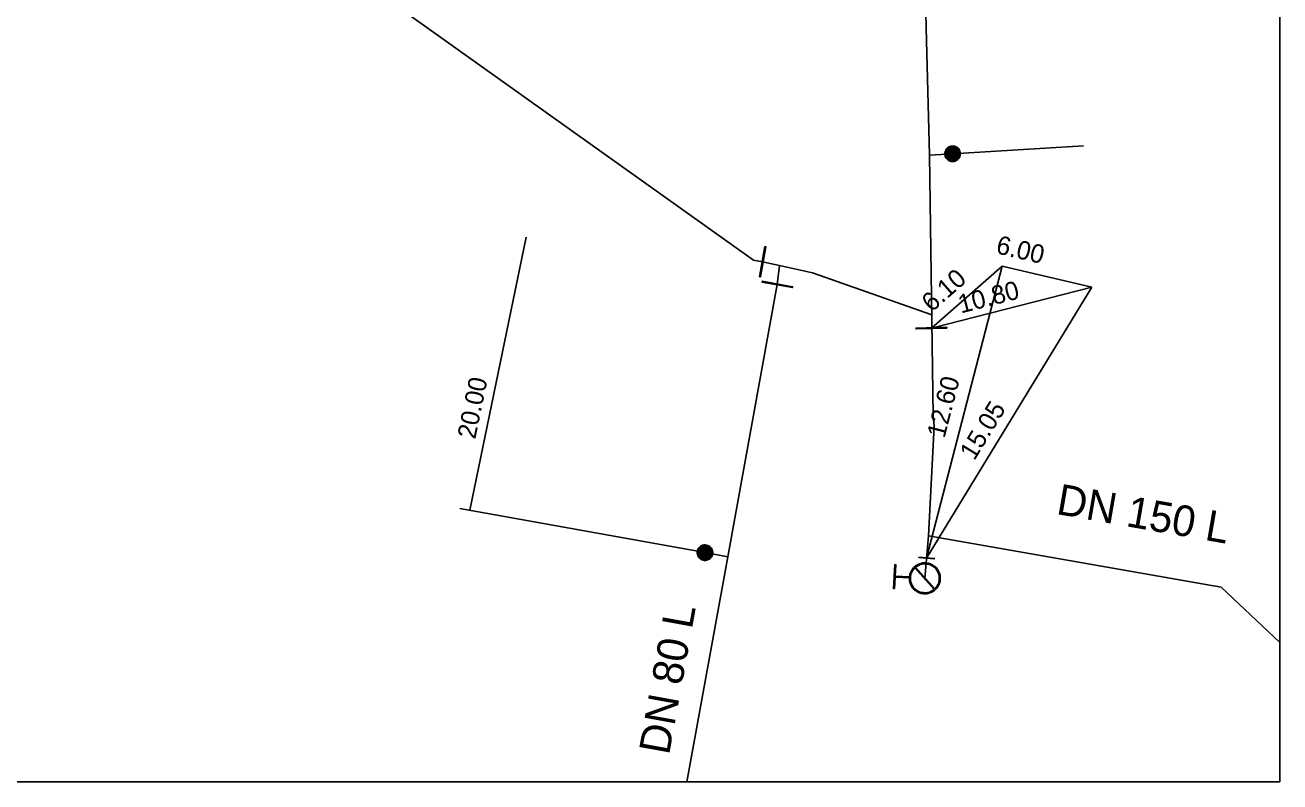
# Model space of a CAD drawing. Extents: x -820257 to -819974, y -1070894 to -1070484.
# Drawn here: x -820057.3 to -819975.6, y -1070893.9 to -1070844.7 of the extents above; entities that cross this region are included whole.
import ezdxf

# ---------------------------------------------------------------- set-up
doc = ezdxf.new("R2010")
doc.units = 0
for name, color, linetype in [('Default', 7, 'Continuous'), ('Hyd-odbočka', 7, 'Continuous'), ('Hyd-šoupě', 7, 'Continuous'), ('Hydrant', 7, 'Continuous'), ('Oměrka vodovodu', 7, 'Continuous'), ('Oměrka-text', 7, 'Continuous'), ('Přípojka vodovodu', 7, 'Continuous'), ('Přípojkový uzávěr', 7, 'Continuous'), ('Roz-řad', 7, 'Continuous'), ('Roz-řad-popis základní', 7, 'Continuous'), ('Řad-šoupě', 7, 'Continuous')]:
    doc.layers.add(name, color=color, linetype=linetype)

msp = doc.modelspace()

# ---------------------------------------------------------------- linework, layer by layer
at = {"layer": 'Default'}
for p, q in [((-819975.603, -1070893.932), (-819975.603, -1070484.403)), ((-820256.81, -1070893.932), (-819975.603, -1070893.932))]:
    msp.add_line(p, q, dxfattribs=at)
at = {"layer": 'Hyd-odbočka'}
msp.add_line((-819998.473, -1070877.929), (-819998.717, -1070880.686), dxfattribs=at)
at = {"layer": 'Hyd-šoupě'}
msp.add_lwpolyline([(-819999.097, -1070879.303), (-819998.101, -1070879.391), (-819998.103, -1070879.422), (-819999.099, -1070879.334), (-819999.097, -1070879.303)], dxfattribs=at)
at = {"layer": 'Hydrant'}
for points in [[(-819999.717, -1070880.661), (-820000.653, -1070880.609), (-820000.695, -1070881.358), (-820000.757, -1070881.354), (-820000.67, -1070879.794), (-820000.607, -1070879.798), (-820000.649, -1070880.546), (-819999.713, -1070880.599)], [(-819998.113, -1070881.407), (-819999.365, -1070880.006)], [(-819999.32, -1070879.966), (-819998.066, -1070881.366)]]:
    msp.add_lwpolyline(points, dxfattribs=at)
for points in [[(-819999.713, -1070880.599), (-819999.692, -1070880.363), (-819999.559, -1070880.146), (-819999.417, -1070879.915), (-819999.169, -1070879.794), (-819998.922, -1070879.673), (-819998.661, -1070879.688), (-819998.401, -1070879.702), (-819998.171, -1070879.847), (-819997.94, -1070879.992), (-819997.822, -1070880.238), (-819997.704, -1070880.483), (-819997.718, -1070880.742), (-819997.733, -1070881.002), (-819997.878, -1070881.232), (-819998.023, -1070881.463), (-819998.268, -1070881.581), (-819998.513, -1070881.699), (-819998.773, -1070881.685), (-819999.034, -1070881.67), (-819999.266, -1070881.522), (-819999.499, -1070881.374), (-819999.614, -1070881.129), (-819999.722, -1070880.9), (-819999.717, -1070880.661)], [(-819999.365, -1070880.006), (-819999.446, -1070880.084), (-819999.506, -1070880.18), (-819999.639, -1070880.398), (-819999.653, -1070880.634), (-819999.666, -1070880.87), (-819999.558, -1070881.101), (-819999.449, -1070881.332), (-819999.232, -1070881.47), (-819999.015, -1070881.608), (-819998.769, -1070881.622), (-819998.525, -1070881.636), (-819998.296, -1070881.524), (-819998.196, -1070881.476), (-819998.113, -1070881.407)], [(-819998.066, -1070881.366), (-819997.99, -1070881.292), (-819997.932, -1070881.198), (-819997.794, -1070880.982), (-819997.781, -1070880.739), (-819997.767, -1070880.495), (-819997.878, -1070880.265), (-819997.99, -1070880.035), (-819998.205, -1070879.899), (-819998.42, -1070879.764), (-819998.664, -1070879.75), (-819998.91, -1070879.736), (-819999.141, -1070879.851), (-819999.24, -1070879.9), (-819999.32, -1070879.966)]]:
    msp.add_open_spline(points, degree=3, dxfattribs=at)
at = {"layer": 'Oměrka vodovodu'}
for p, q in [((-820028.34, -1070876.249), (-820024.68, -1070858.484)), ((-819998.6, -1070879.363), (-819993.684, -1070860.366)), ((-819998.29, -1070864.406), (-819993.684, -1070860.366)), ((-819993.684, -1070860.366), (-819987.841, -1070861.73)), ((-819998.6, -1070879.363), (-819987.841, -1070861.73)), ((-819998.29, -1070864.406), (-819987.841, -1070861.73))]:
    msp.add_line(p, q, dxfattribs=at)
at = {"layer": 'Přípojka vodovodu'}
for points in [[(-819998.405, -1070853.152), (-819996.908, -1070853.059), (-819988.393, -1070852.533)], [(-820011.552, -1070879.28), (-820013.027, -1070879.013), (-820028.996, -1070876.131)]]:
    msp.add_lwpolyline(points, dxfattribs=at)
at = {"layer": 'Přípojkový uzávěr'}
for points in [[(-819996.939, -1070852.56), (-819996.813, -1070852.552), (-819996.69, -1070852.609), (-819996.567, -1070852.666), (-819996.492, -1070852.782), (-819996.417, -1070852.898), (-819996.409, -1070853.029), (-819996.401, -1070853.158), (-819996.459, -1070853.281), (-819996.518, -1070853.404), (-819996.632, -1070853.477), (-819996.747, -1070853.55), (-819996.877, -1070853.558), (-819997.007, -1070853.566), (-819997.13, -1070853.508), (-819997.253, -1070853.449), (-819997.326, -1070853.335), (-819997.399, -1070853.22), (-819997.407, -1070853.09), (-819997.415, -1070852.96), (-819997.355, -1070852.836), (-819997.296, -1070852.711), (-819997.181, -1070852.64), (-819997.065, -1070852.568), (-819996.939, -1070852.56)], [(-819996.936, -1070852.607), (-819997.05, -1070852.614), (-819997.155, -1070852.679), (-819997.259, -1070852.744), (-819997.313, -1070852.856), (-819997.367, -1070852.969), (-819997.36, -1070853.088), (-819997.353, -1070853.205), (-819997.287, -1070853.309), (-819997.221, -1070853.413), (-819997.109, -1070853.466), (-819996.997, -1070853.519), (-819996.88, -1070853.511), (-819996.762, -1070853.504), (-819996.658, -1070853.438), (-819996.554, -1070853.371), (-819996.501, -1070853.26), (-819996.448, -1070853.149), (-819996.456, -1070853.032), (-819996.463, -1070852.913), (-819996.531, -1070852.808), (-819996.599, -1070852.703), (-819996.711, -1070852.651), (-819996.822, -1070852.6), (-819996.936, -1070852.607)], [(-819996.934, -1070852.641), (-819996.828, -1070852.634), (-819996.725, -1070852.682), (-819996.622, -1070852.73), (-819996.559, -1070852.827), (-819996.496, -1070852.924), (-819996.49, -1070853.034), (-819996.483, -1070853.142), (-819996.532, -1070853.245), (-819996.58, -1070853.348), (-819996.677, -1070853.409), (-819996.773, -1070853.471), (-819996.882, -1070853.477), (-819996.991, -1070853.484), (-819997.094, -1070853.435), (-819997.197, -1070853.386), (-819997.258, -1070853.29), (-819997.319, -1070853.194), (-819997.326, -1070853.085), (-819997.333, -1070852.976), (-819997.283, -1070852.872), (-819997.233, -1070852.768), (-819997.136, -1070852.708), (-819997.039, -1070852.647), (-819996.934, -1070852.641)], [(-819996.932, -1070852.685), (-819997.088, -1070852.695), (-819997.19, -1070852.811), (-819997.292, -1070852.927), (-819997.282, -1070853.083), (-819997.272, -1070853.238), (-819997.156, -1070853.34), (-819997.04, -1070853.443), (-819996.886, -1070853.433), (-819996.73, -1070853.424), (-819996.627, -1070853.308), (-819996.524, -1070853.191), (-819996.533, -1070853.036), (-819996.543, -1070852.881), (-819996.659, -1070852.778), (-819996.775, -1070852.675), (-819996.932, -1070852.685)], [(-819996.929, -1070852.731), (-819996.792, -1070852.722), (-819996.691, -1070852.812), (-819996.59, -1070852.902), (-819996.581, -1070853.038), (-819996.573, -1070853.174), (-819996.663, -1070853.276), (-819996.753, -1070853.377), (-819996.889, -1070853.386), (-819997.025, -1070853.394), (-819997.126, -1070853.304), (-819997.228, -1070853.214), (-819997.236, -1070853.078), (-819997.245, -1070852.942), (-819997.155, -1070852.841), (-819997.066, -1070852.739), (-819996.929, -1070852.731)], [(-819996.927, -1070852.77), (-819997.047, -1070852.778), (-819997.125, -1070852.867), (-819997.204, -1070852.957), (-819997.197, -1070853.076), (-819997.189, -1070853.195), (-819997.1, -1070853.275), (-819997.011, -1070853.354), (-819996.891, -1070853.346), (-819996.772, -1070853.339), (-819996.693, -1070853.249), (-819996.613, -1070853.16), (-819996.621, -1070853.04), (-819996.628, -1070852.921), (-819996.717, -1070852.842), (-819996.806, -1070852.763), (-819996.927, -1070852.77)], [(-819996.924, -1070852.81), (-819996.819, -1070852.803), (-819996.742, -1070852.872), (-819996.665, -1070852.94), (-819996.658, -1070853.044), (-819996.652, -1070853.147), (-819996.72, -1070853.225), (-819996.789, -1070853.302), (-819996.893, -1070853.309), (-819996.996, -1070853.315), (-819997.073, -1070853.247), (-819997.151, -1070853.178), (-819997.157, -1070853.075), (-819997.164, -1070852.971), (-819997.096, -1070852.894), (-819997.028, -1070852.816), (-819996.924, -1070852.81)], [(-819996.921, -1070852.856), (-819997.005, -1070852.861), (-819997.061, -1070852.924), (-819997.116, -1070852.987), (-819997.111, -1070853.071), (-819997.106, -1070853.155), (-819997.043, -1070853.211), (-819996.98, -1070853.267), (-819996.896, -1070853.261), (-819996.812, -1070853.256), (-819996.756, -1070853.193), (-819996.7, -1070853.13), (-819996.706, -1070853.046), (-819996.711, -1070852.962), (-819996.774, -1070852.906), (-819996.837, -1070852.851), (-819996.921, -1070852.856)], [(-819996.919, -1070852.891), (-819996.849, -1070852.886), (-819996.797, -1070852.932), (-819996.745, -1070852.978), (-819996.74, -1070853.048), (-819996.736, -1070853.118), (-819996.782, -1070853.17), (-819996.828, -1070853.222), (-819996.898, -1070853.227), (-819996.968, -1070853.231), (-819997.02, -1070853.185), (-819997.072, -1070853.139), (-819997.076, -1070853.069), (-819997.081, -1070852.999), (-819997.035, -1070852.947), (-819996.989, -1070852.895), (-819996.919, -1070852.891)], [(-819996.916, -1070852.934), (-819996.968, -1070852.938), (-819997.002, -1070852.976), (-819997.036, -1070853.015), (-819997.033, -1070853.067), (-819997.029, -1070853.118), (-819996.991, -1070853.153), (-819996.952, -1070853.187), (-819996.901, -1070853.184), (-819996.848, -1070853.181), (-819996.814, -1070853.142), (-819996.78, -1070853.103), (-819996.783, -1070853.051), (-819996.786, -1070853), (-819996.825, -1070852.965), (-819996.863, -1070852.931), (-819996.916, -1070852.934)], [(-819996.913, -1070852.981), (-819996.88, -1070852.979), (-819996.856, -1070853), (-819996.832, -1070853.021), (-819996.83, -1070853.054), (-819996.828, -1070853.086), (-819996.849, -1070853.111), (-819996.87, -1070853.135), (-819996.903, -1070853.137), (-819996.936, -1070853.139), (-819996.96, -1070853.118), (-819996.984, -1070853.096), (-819996.986, -1070853.064), (-819996.988, -1070853.031), (-819996.967, -1070853.007), (-819996.945, -1070852.983), (-819996.913, -1070852.981)], [(-819996.911, -1070853.012), (-819996.931, -1070853.014), (-819996.944, -1070853.028), (-819996.956, -1070853.042), (-819996.955, -1070853.062), (-819996.954, -1070853.082), (-819996.939, -1070853.094), (-819996.925, -1070853.107), (-819996.905, -1070853.106), (-819996.885, -1070853.105), (-819996.873, -1070853.09), (-819996.86, -1070853.076), (-819996.862, -1070853.056), (-819996.863, -1070853.036), (-819996.877, -1070853.024), (-819996.891, -1070853.011), (-819996.911, -1070853.012)], [(-820012.939, -1070878.521), (-820012.815, -1070878.543), (-820012.709, -1070878.628), (-820012.602, -1070878.712), (-820012.557, -1070878.843), (-820012.512, -1070878.973), (-820012.535, -1070879.102), (-820012.558, -1070879.23), (-820012.644, -1070879.335), (-820012.73, -1070879.44), (-820012.859, -1070879.484), (-820012.988, -1070879.528), (-820013.116, -1070879.505), (-820013.244, -1070879.482), (-820013.349, -1070879.396), (-820013.455, -1070879.31), (-820013.499, -1070879.181), (-820013.542, -1070879.052), (-820013.519, -1070878.924), (-820013.496, -1070878.796), (-820013.409, -1070878.689), (-820013.321, -1070878.583), (-820013.192, -1070878.54), (-820013.063, -1070878.498), (-820012.939, -1070878.521)], [(-820012.947, -1070878.567), (-820013.06, -1070878.546), (-820013.177, -1070878.585), (-820013.294, -1070878.623), (-820013.373, -1070878.719), (-820013.452, -1070878.816), (-820013.473, -1070878.933), (-820013.494, -1070879.049), (-820013.455, -1070879.165), (-820013.415, -1070879.282), (-820013.319, -1070879.36), (-820013.223, -1070879.438), (-820013.108, -1070879.459), (-820012.992, -1070879.48), (-820012.875, -1070879.44), (-820012.758, -1070879.4), (-820012.68, -1070879.305), (-820012.602, -1070879.21), (-820012.581, -1070879.094), (-820012.56, -1070878.977), (-820012.601, -1070878.859), (-820012.643, -1070878.74), (-820012.739, -1070878.664), (-820012.835, -1070878.587), (-820012.947, -1070878.567)], [(-820012.953, -1070878.6), (-820012.849, -1070878.619), (-820012.76, -1070878.69), (-820012.672, -1070878.761), (-820012.633, -1070878.87), (-820012.595, -1070878.98), (-820012.615, -1070879.088), (-820012.634, -1070879.195), (-820012.706, -1070879.283), (-820012.778, -1070879.371), (-820012.886, -1070879.408), (-820012.994, -1070879.444), (-820013.102, -1070879.425), (-820013.209, -1070879.406), (-820013.297, -1070879.334), (-820013.386, -1070879.262), (-820013.422, -1070879.154), (-820013.459, -1070879.046), (-820013.439, -1070878.939), (-820013.42, -1070878.831), (-820013.347, -1070878.741), (-820013.274, -1070878.652), (-820013.165, -1070878.617), (-820013.057, -1070878.582), (-820012.953, -1070878.6)], [(-820012.961, -1070878.644), (-820013.115, -1070878.616), (-820013.242, -1070878.705), (-820013.369, -1070878.793), (-820013.396, -1070878.947), (-820013.424, -1070879.099), (-820013.335, -1070879.227), (-820013.247, -1070879.354), (-820013.095, -1070879.382), (-820012.941, -1070879.409), (-820012.813, -1070879.321), (-820012.686, -1070879.233), (-820012.658, -1070879.08), (-820012.631, -1070878.927), (-820012.718, -1070878.799), (-820012.806, -1070878.672), (-820012.961, -1070878.644)], [(-820012.97, -1070878.689), (-820012.835, -1070878.713), (-820012.758, -1070878.824), (-820012.681, -1070878.936), (-820012.705, -1070879.07), (-820012.729, -1070879.204), (-820012.841, -1070879.281), (-820012.952, -1070879.359), (-820013.086, -1070879.335), (-820013.221, -1070879.31), (-820013.298, -1070879.199), (-820013.375, -1070879.087), (-820013.351, -1070878.953), (-820013.327, -1070878.819), (-820013.215, -1070878.742), (-820013.104, -1070878.664), (-820012.97, -1070878.689)], [(-820012.977, -1070878.728), (-820013.095, -1070878.706), (-820013.193, -1070878.774), (-820013.291, -1070878.843), (-820013.312, -1070878.96), (-820013.333, -1070879.078), (-820013.265, -1070879.176), (-820013.197, -1070879.274), (-820013.079, -1070879.296), (-820012.961, -1070879.317), (-820012.863, -1070879.249), (-820012.765, -1070879.181), (-820012.744, -1070879.063), (-820012.723, -1070878.945), (-820012.79, -1070878.847), (-820012.858, -1070878.749), (-820012.977, -1070878.728)], [(-820012.983, -1070878.767), (-820012.88, -1070878.785), (-820012.821, -1070878.87), (-820012.763, -1070878.955), (-820012.781, -1070879.058), (-820012.8, -1070879.16), (-820012.885, -1070879.218), (-820012.97, -1070879.277), (-820013.072, -1070879.259), (-820013.173, -1070879.24), (-820013.233, -1070879.156), (-820013.292, -1070879.071), (-820013.273, -1070878.969), (-820013.255, -1070878.866), (-820013.17, -1070878.807), (-820013.086, -1070878.748), (-820012.983, -1070878.767)], [(-820012.991, -1070878.812), (-820013.075, -1070878.797), (-820013.143, -1070878.845), (-820013.212, -1070878.893), (-820013.227, -1070878.976), (-820013.242, -1070879.059), (-820013.195, -1070879.128), (-820013.147, -1070879.197), (-820013.064, -1070879.212), (-820012.981, -1070879.227), (-820012.912, -1070879.179), (-820012.843, -1070879.131), (-820012.828, -1070879.048), (-820012.813, -1070878.965), (-820012.86, -1070878.896), (-820012.908, -1070878.827), (-820012.991, -1070878.812)], [(-820012.998, -1070878.846), (-820012.928, -1070878.859), (-820012.889, -1070878.916), (-820012.849, -1070878.973), (-820012.862, -1070879.042), (-820012.874, -1070879.111), (-820012.931, -1070879.151), (-820012.989, -1070879.19), (-820013.057, -1070879.178), (-820013.127, -1070879.165), (-820013.166, -1070879.108), (-820013.206, -1070879.051), (-820013.193, -1070878.982), (-820013.181, -1070878.913), (-820013.124, -1070878.874), (-820013.067, -1070878.834), (-820012.998, -1070878.846)], [(-820013.005, -1070878.89), (-820013.056, -1070878.88), (-820013.099, -1070878.91), (-820013.141, -1070878.94), (-820013.15, -1070878.991), (-820013.159, -1070879.042), (-820013.13, -1070879.084), (-820013.1, -1070879.127), (-820013.05, -1070879.136), (-820012.998, -1070879.145), (-820012.956, -1070879.115), (-820012.913, -1070879.086), (-820012.904, -1070879.035), (-820012.895, -1070878.984), (-820012.924, -1070878.942), (-820012.954, -1070878.899), (-820013.005, -1070878.89)], [(-820013.014, -1070878.936), (-820012.981, -1070878.942), (-820012.963, -1070878.968), (-820012.945, -1070878.994), (-820012.951, -1070879.027), (-820012.956, -1070879.058), (-820012.983, -1070879.077), (-820013.009, -1070879.095), (-820013.041, -1070879.09), (-820013.073, -1070879.084), (-820013.092, -1070879.057), (-820013.11, -1070879.031), (-820013.104, -1070878.999), (-820013.099, -1070878.966), (-820013.072, -1070878.948), (-820013.045, -1070878.93), (-820013.014, -1070878.936)], [(-820013.019, -1070878.967), (-820013.039, -1070878.963), (-820013.054, -1070878.974), (-820013.07, -1070878.985), (-820013.074, -1070879.004), (-820013.077, -1070879.024), (-820013.066, -1070879.039), (-820013.055, -1070879.055), (-820013.036, -1070879.059), (-820013.016, -1070879.062), (-820013.001, -1070879.051), (-820012.985, -1070879.04), (-820012.981, -1070879.021), (-820012.978, -1070879.001), (-820012.989, -1070878.986), (-820013, -1070878.97), (-820013.019, -1070878.967)]]:
    msp.add_open_spline(points, degree=3, dxfattribs=at)
at = {"layer": 'Roz-řad'}
for p, q in [((-820008.177, -1070860.335), (-820009.275, -1070860.089)), ((-820008.32, -1070861.56), (-820008.177, -1070860.335)), ((-819998.118, -1070870.78), (-819998.171, -1070870.117)), ((-819998.473, -1070877.929), (-819998.118, -1070870.78))]:
    msp.add_line(p, q, dxfattribs=at)
for points in [[(-819998.171, -1070870.117), (-819998.405, -1070853.152), (-819998.628, -1070844.86), (-819999.183, -1070819.957), (-819999.443, -1070808.28), (-820000.085, -1070782.958), (-820000.381, -1070772.161), (-820000.485, -1070768.618)], [(-820009.275, -1070860.089), (-820009.863, -1070859.992), (-820044.329, -1070835.435), (-820068.948, -1070817.938), (-820083.25, -1070815.478)], [(-820008.177, -1070860.335), (-820006.031, -1070860.803), (-819998.262, -1070863.539)], [(-820014.208, -1070893.932), (-820011.552, -1070879.28), (-820008.32, -1070861.56)], [(-819975.603, -1070884.871), (-819979.432, -1070881.255), (-819998.473, -1070877.929)]]:
    msp.add_lwpolyline(points, dxfattribs=at)
at = {"layer": 'Řad-šoupě'}
for points in [[(-820009.485, -1070861.066), (-820009.126, -1070859.098), (-820009.064, -1070859.11), (-820009.423, -1070861.077), (-820009.485, -1070861.066)], [(-820009.297, -1070861.348), (-820007.329, -1070861.707), (-820007.341, -1070861.769), (-820009.308, -1070861.41), (-820009.297, -1070861.348)], [(-819997.29, -1070864.413), (-819999.289, -1070864.461), (-819999.29, -1070864.398), (-819997.291, -1070864.351), (-819997.29, -1070864.413)]]:
    msp.add_lwpolyline(points, dxfattribs=at)

# ---------------------------------------------------------------- texts
at = {"layer": 'Oměrka-text'}
for s, rotation, p in [(' 6.00', 346.86011, (-819994.575, -1070859.422)), (' 6.10', 41.25457, (-819998.605, -1070863.697)), ('10.80', 14.3648, (-819996.371, -1070863.454)), ('20.00', 78.35862, (-820027.986, -1070871.674)), ('12.60', 75.49143, (-819997.44, -1070871.614)), ('15.05', 58.61003, (-819995.497, -1070873.072))]:
    msp.add_text(s, height=1.2, rotation=rotation, dxfattribs=at).set_placement(p)
at = {"layer": 'Roz-řad-popis základní'}
for s, rotation, p in [('DN 150 L', 350.09177, (-819990.219, -1070876.493)), ('DN 80 L', 79.72685, (-820015.37, -1070892.232))]:
    msp.add_text(s, height=2, rotation=rotation, dxfattribs=at).set_placement(p)

doc.saveas('drawing.dxf')
